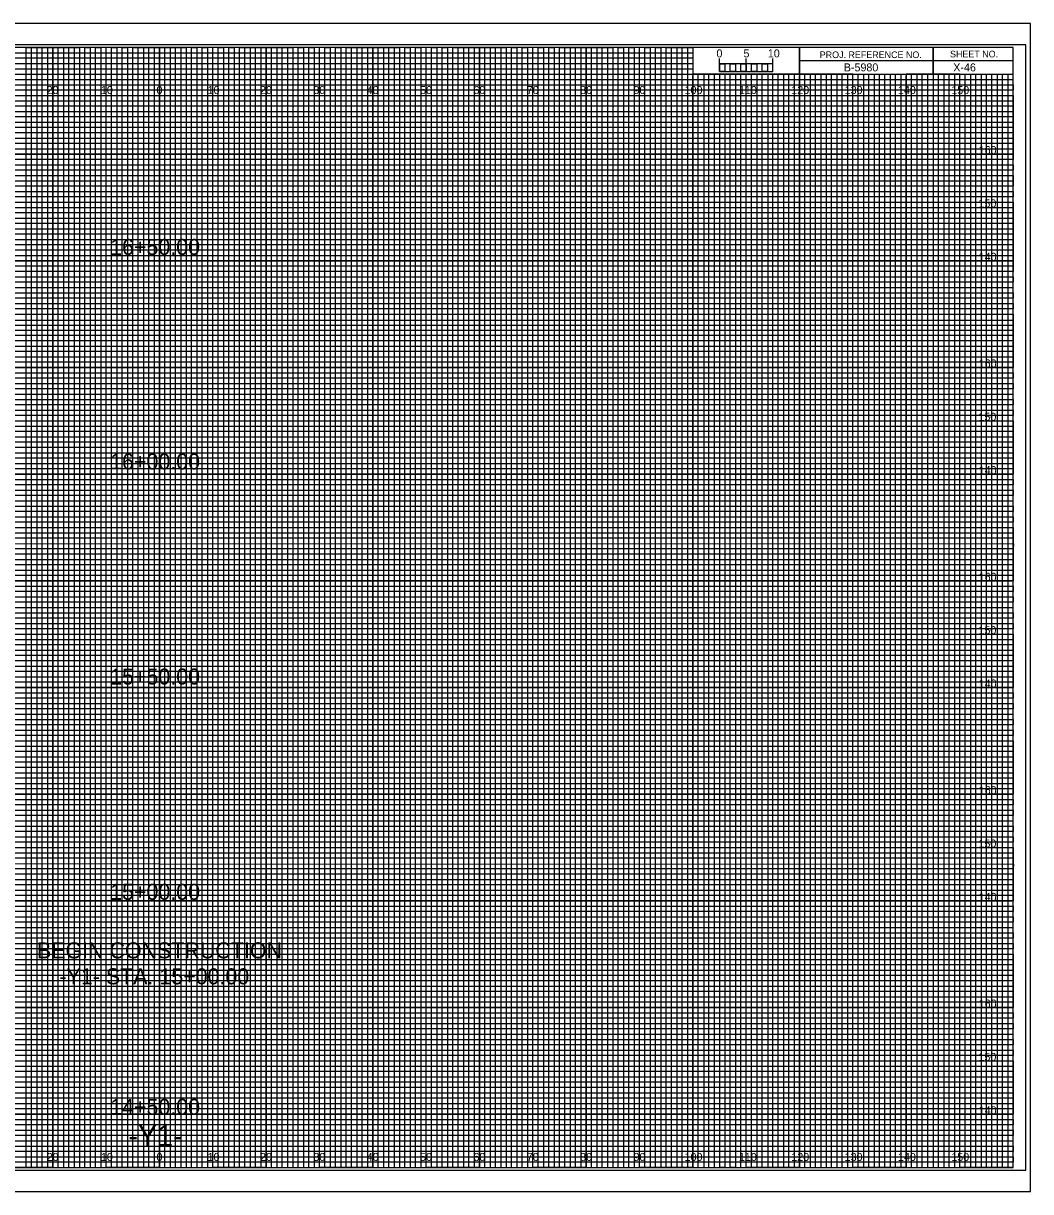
# Model space of a CAD drawing. Extents: x -13 to 323, y -5 to 4834.
# Drawn here: x 134.5 to 323.3, y -4.5 to 214.5 of the extents above; entities that cross this region are included whole.
import ezdxf

# ---------------------------------------------------------------- set-up
doc = ezdxf.new("R2010")
doc.units = 0
for name, color, linetype in [('Exist CMT Pavement', 7, 'Continuous'), ('Exist Cross Section Cell', 7, 'Continuous'), ('Exist XS Center Line Elevation Label', 7, 'Continuous'), ('Exist XS Ground Line', 7, 'Continuous'), ('Prop CMT Pvmt Course 1', 7, 'Continuous'), ('Prop CMT Pvmt Course 1 Wedge', 7, 'Continuous'), ('Prop CMT Pvmt Course 2', 7, 'Continuous'), ('Prop CMT Pvmt Course 2 Wedge', 7, 'Continuous'), ('Prop CMT Pvmt Course 3', 7, 'Continuous'), ('Prop CMT Pvmt Course 3 Wedge', 7, 'Continuous'), ('Prop CMT Pvmt Surface', 7, 'Continuous'), ('Prop CMT Pvmt Surface Shoulder', 7, 'Continuous'), ('Prop CMT Shld Paved Course 1', 7, 'Continuous'), ('Prop CMT Shld Paved Course 2', 7, 'Continuous'), ('Prop CMT Shld Paved Course 3', 7, 'Continuous'), ('Prop CMT Slope Grass', 7, 'Continuous'), ('Prop CMT Subgrade Earthwork', 7, 'Continuous')]:
    doc.layers.add(name, color=color, linetype=linetype)

msp = doc.modelspace()

# ---------------------------------------------------------------- linework, layer by layer
at = {"layer": 'Exist XS Center Line Elevation Label'}
for points in [[(125, 0), (135, 0), (135, 210), (145, 210), (145, 0), (155, 0), (155, 210), (165, 210), (165, 0), (175, 0), (175, 210), (185, 210), (185, 0), (195, 0), (195, 210), (205, 210), (205, 0), (215, 0), (215, 210), (225, 210), (225, 0), (235, 0), (235, 210), (245, 210), (245, 0), (255, 0), (255, 210), (259.93, 210), (260, 210), (260, 205), (264.99, 205), (264.99, 0), (275, 0), (275, 205), (285, 205), (285, 0), (295, 0), (295, 205), (305, 205), (305, 0), (315, 0), (315, 205)], [(0, 205), (275, 205)], [(0, 185), (320, 185), (320, 195), (0, 195)], [(0, 165), (320, 165), (320, 175), (0, 175)], [(0, 145), (320, 145), (320, 155), (0, 155)], [(0, 125), (320, 125), (320, 135), (0, 135)], [(0, 105), (320, 105), (320, 115), (0, 115)], [(0, 85), (320, 85), (320, 95), (0, 95)], [(0, 65), (320, 65), (320, 75), (0, 75)], [(0, 45), (320, 45), (320, 55), (0, 55)], [(0, 25), (320, 25), (320, 35), (0, 35)], [(0, 5), (320, 5), (320, 15), (0, 15)]]:
    msp.add_lwpolyline(points, dxfattribs=at)
at = {"layer": 'Exist XS Ground Line'}
for p, q in [((150, 210), (140, 210)), ((140, 210), (140, 0)), ((150, 0), (150, 210)), ((170, 210), (160, 210)), ((160, 210), (160, 0)), ((170, 0), (170, 210)), ((190, 210), (180, 210)), ((180, 210), (180, 0)), ((190, 0), (190, 210)), ((210, 210), (200, 210)), ((200, 210), (200, 0)), ((210, 0), (210, 210)), ((230, 210), (220, 210)), ((220, 210), (220, 0)), ((230, 0), (230, 210)), ((250, 210), (240, 210)), ((240, 210), (240, 0)), ((250, 0), (250, 210)), ((260, 210), (260, 0)), ((270, 0), (270, 205)), ((290, 205), (280, 205)), ((280, 205), (280, 0)), ((290, 0), (290, 205)), ((310, 205), (300, 205)), ((300, 205), (300, 0)), ((310, 0), (310, 205)), ((140, 0), (130, 0)), ((160, 0), (150, 0)), ((180, 0), (170, 0)), ((200, 0), (190, 0)), ((220, 0), (210, 0)), ((240, 0), (230, 0)), ((260, 0), (250, 0)), ((280, 0), (270, 0)), ((300, 0), (290, 0)), ((320, 0), (310, 0)), ((320, 0), (320, 0))]:
    msp.add_line(p, q, dxfattribs=at)
for points in [[(0, 200), (320, 200), (320, 190), (0, 190)], [(0, 180), (320, 180), (320, 170), (0, 170)], [(0, 160), (320, 160), (320, 150), (0, 150)], [(0, 140), (320, 140), (320, 130), (0, 130)], [(0, 120), (320, 120), (320, 110), (0, 110)], [(0, 100), (320, 100), (320, 90), (0, 90)], [(0, 80), (320, 80), (320, 70), (0, 70)], [(0, 60), (320, 60), (320, 50), (0, 50)], [(0, 40), (320, 40), (320, 30), (0, 30)], [(0, 20), (320, 20), (320, 10), (0, 10)]]:
    msp.add_lwpolyline(points, dxfattribs=at)
at = {"layer": 'Prop CMT Pvmt Course 1'}
for p, q in [((267, 205), (266.01, 205)), ((266.01, 205), (266.01, 0)), ((267, 0), (267, 205)), ((269, 205), (268, 205)), ((268, 205), (268, 0)), ((269, 0), (269, 205)), ((266.01, 0), (265, 0)), ((268, 0), (267, 0))]:
    msp.add_line(p, q, dxfattribs=at)
for points in [[(135, 0), (136, 0), (136, 210), (137, 210), (137, 0)], [(137, 0), (138, 0), (138, 210), (139, 210), (139, 0)], [(140, 0), (141, 0), (141, 210), (142, 210), (142, 0)], [(142, 0), (143, 0), (143, 210), (144, 210), (144, 0)], [(145, 0), (146, 0), (146, 210), (147, 210), (147, 0)], [(147, 0), (148, 0), (148, 210), (149, 210), (149, 0)], [(150, 0), (151, 0), (151, 210), (152, 210), (152, 0)], [(152, 0), (153, 0), (153, 210), (154, 210), (154, 0)], [(155, 0), (156, 0), (156, 210), (157, 210), (157, 0)], [(157, 0), (158, 0), (158, 210), (159, 210), (159, 0)], [(160, 0), (161, 0), (161, 210), (162, 210), (162, 0)], [(162, 0), (163, 0), (163, 210), (164, 210), (164, 0)], [(165, 0), (166, 0), (166, 210), (167, 210), (167, 0)], [(167, 0), (168, 0), (168, 210), (169, 210), (169, 0)], [(170, 0), (171, 0), (171, 210), (172, 210), (172, 0)], [(172, 0), (173, 0), (173, 210), (174, 210), (174, 0)], [(175, 0), (176, 0), (176, 210), (177, 210), (177, 0)], [(177, 0), (178, 0), (178, 210), (179, 210), (179, 0)], [(180, 0), (181, 0), (181, 210), (182, 210), (182, 0)], [(182, 0), (183, 0), (183, 210), (184, 210), (184, 0)], [(185, 0), (186, 0), (186, 210), (187, 210), (187, 0)], [(187, 0), (188, 0), (188, 210), (189, 210), (189, 0)], [(190, 0), (191, 0), (191, 210), (192, 210), (192, 0)], [(192, 0), (193, 0), (193, 210), (194, 210), (194, 0)], [(195, 0), (196, 0), (196, 210), (197, 210), (197, 0)], [(197, 0), (198, 0), (198, 210), (199, 210), (199, 0)], [(200, 0), (201, 0), (201, 210), (202, 210), (202, 0)], [(202, 0), (203, 0), (203, 210), (204, 210), (204, 0)], [(205, 0), (206, 0), (206, 210), (207, 210), (207, 0)], [(207, 0), (208, 0), (208, 210), (209, 210), (209, 0)], [(210, 0), (211, 0), (211, 210), (212, 210), (212, 0)], [(212, 0), (213, 0), (213, 210), (214, 210), (214, 0)], [(215, 0), (216, 0), (216, 210), (217, 210), (217, 0)], [(217, 0), (218, 0), (218, 210), (219, 210), (219, 0)], [(220, 0), (221, 0), (221, 210), (222, 210), (222, 0)], [(222, 0), (223, 0), (223, 210), (224, 210), (224, 0)], [(225, 0), (226, 0), (226, 210), (227, 210), (227, 0)], [(227, 0), (228, 0), (228, 210), (229, 210), (229, 0)], [(230, 0), (231, 0), (231, 210), (232, 210), (232, 0)], [(232, 0), (233, 0), (233, 210), (234, 210), (234, 0)], [(235, 0), (236, 0), (236, 210), (237, 210), (237, 0)], [(237, 0), (238, 0), (238, 210), (239, 210), (239, 0)], [(240, 0), (241, 0), (241, 210), (242, 210), (242, 0)], [(242, 0), (243, 0), (243, 210), (244, 210), (244, 0)], [(245, 0), (246, 0), (246, 210), (247, 210), (247, 0)], [(247, 0), (248, 0), (248, 210), (249, 210), (249, 0)], [(250, 0), (251, 0), (251, 210), (252, 210), (252, 0)], [(252, 0), (253, 0), (253, 210), (254, 210), (254, 0)], [(255, 0), (256, 0), (256, 210), (257, 210), (257, 0)], [(257, 0), (258, 0), (258, 210), (259, 210), (259, 0)], [(260, 0), (261, 0), (261, 205), (262.02, 205), (262.02, 0)], [(262, 0), (263, 0), (263, 205), (263.99, 205), (263.99, 0)], [(270, 0), (270.98, 0), (270.98, 205), (272, 205), (272, 0)], [(272, 0), (273, 0), (273, 205), (274.05, 205), (274.05, 0)], [(275, 0), (276, 0), (276, 205), (277, 205), (277, 0)], [(277, 0), (278, 0), (278, 205), (279, 205), (279, 0)], [(280, 0), (281, 0), (281, 205), (282, 205), (282, 0)], [(282, 0), (283, 0), (283, 205), (284, 205), (284, 0)], [(285, 0), (286, 0), (286, 205), (287, 205), (287, 0)], [(287, 0), (288, 0), (288, 205), (289, 205), (289, 0)], [(290, 0), (291, 0), (291, 205), (292, 205), (292, 0)], [(292, 0), (293, 0), (293, 205), (294, 205), (294, 0)], [(295, 0), (296, 0), (296, 205), (297, 205), (297, 0)], [(297, 0), (298, 0), (298, 205), (299, 205), (299, 0)], [(300, 0), (301, 0), (301, 205), (302, 205), (302, 0)], [(302, 0), (303, 0), (303, 205), (304, 205), (304, 0)], [(305, 0), (306, 0), (306, 205), (307, 205), (307, 0)], [(307, 0), (308, 0), (308, 205), (309, 205), (309, 0)], [(310, 0), (311, 0), (311, 205), (312, 205), (312, 0)], [(312, 0), (313, 0), (313, 205), (314, 205), (314, 0)], [(315, 0), (316, 0), (316, 205), (317, 205), (317, 0)], [(317, 0), (318, 0), (318, 205), (319, 205), (319, 0)]]:
    msp.add_lwpolyline(points, dxfattribs=at)
at = {"layer": 'Prop CMT Pvmt Course 2'}
for p, q in [((323.3, 214.5), (-13.4, 214.5)), ((-13.4, -4.5), (323.3, -4.5))]:
    msp.add_line(p, q, dxfattribs=at)
at = {"layer": 'Prop CMT Pvmt Surface Shoulder'}
for p, q in [((305, 210), (305, 205)), ((305, 205), (305, 210)), ((280, 207.5), (280, 205)), ((320, 207.49), (280, 207.49)), ((280, 205), (320, 205))]:
    msp.add_line(p, q, dxfattribs=at)
for points in [[(320, 210), (0, 210), (0, 0), (320, 0)], [(280, 210), (260, 210), (260, 205.03), (280, 205.03)], [(320, 210), (280, 210), (280, 205), (320, 205)]]:
    msp.add_lwpolyline(points, close=True, dxfattribs=at)
at = {"layer": 'Prop CMT Shld Paved Course 1'}
msp.add_lwpolyline([(-13.4, -4.5), (323.3, -4.5), (323.3, 214.5), (-13.4, 214.5)], close=True, dxfattribs=at)
at = {"layer": 'Prop CMT Shld Paved Course 2'}
msp.add_lwpolyline([(-10.8, -0.5), (322.4, -0.5), (322.4, 210.5), (-10.8, 210.5)], close=True, dxfattribs=at)
at = {"layer": 'Prop CMT Shld Paved Course 3'}
for p, q in [((140, 0), (140, 210)), ((150, 0), (150, 210)), ((160, 0), (160, 210)), ((170, 0), (170, 210)), ((180, 0), (180, 210)), ((190, 0), (190, 210)), ((200, 0), (200, 210)), ((210, 0), (210, 210)), ((220, 0), (220, 210)), ((230, 0), (230, 210)), ((240, 0), (240, 210)), ((250, 0), (250, 210)), ((260, 0), (260, 204.69)), ((270, 0), (270, 204.69)), ((280, 0), (280, 204.69)), ((290, 0), (290, 204.69)), ((300, 0), (300, 204.69)), ((310, 0), (310, 204.69)), ((0, 200), (320, 200)), ((0, 190), (320, 190)), ((0, 180), (320, 180)), ((0, 170), (320, 170)), ((0, 160), (320, 160)), ((0, 150), (320, 150)), ((0, 140), (320, 140)), ((0, 130), (320, 130)), ((0, 120), (320, 120)), ((0, 110), (320, 110)), ((0, 100), (320, 100)), ((0, 90), (320, 90)), ((0, 80), (320, 80)), ((0, 70), (320, 70)), ((0, 60), (320, 60)), ((0, 50), (320, 50)), ((0, 40), (320, 40)), ((0, 30), (320, 30)), ((0, 20), (320, 20)), ((0, 10), (320, 10))]:
    msp.add_line(p, q, dxfattribs=at)
at = {"layer": 'Prop CMT Slope Grass'}
for p, q in [((0, 209), (260, 209)), ((260, 209), (260, 207.98)), ((260, 207.98), (0, 207.98)), ((0, 207), (260, 207)), ((260, 205.89), (0, 205.89)), ((260, 207), (260, 205.89)), ((0, 204), (320, 204))]:
    msp.add_line(p, q, dxfattribs=at)
for points in [[(0, 203), (270, 203), (320, 203), (320, 202), (0, 202)], [(0, 201), (320, 201), (320, 199), (0, 199)], [(0, 198), (320, 198), (320, 197), (0, 196.98)], [(0, 196), (320, 196), (320, 194), (0, 194)], [(0, 193), (320, 193), (320, 192), (0, 192)], [(0, 191), (320, 191), (320, 189), (0, 189)], [(0, 188), (320, 188), (320, 187), (0, 187)], [(0, 186), (320, 186), (320, 184), (0, 184)], [(0, 183), (320, 183), (320, 182), (0, 182)], [(0, 181), (320, 181), (320, 179), (0, 179)], [(0, 178), (320, 178), (320, 177), (0, 177)], [(0, 176), (320, 176), (320, 173.95), (320, 173), (320, 172), (0, 172)], [(0, 174), (320, 174), (320, 173), (0, 173)], [(0, 171), (320, 171), (320, 169), (0, 169.03)], [(0, 169.03), (320, 169), (320, 168), (0, 168)], [(0, 167), (320, 167), (320, 166), (0, 166)], [(0, 164), (320, 164), (320, 163), (0, 163)], [(0, 162), (320, 162), (320, 161), (0, 161)], [(-0.07, 158.89), (320, 158.89), (320, 157.88), (-0.07, 157.88)], [(0, 157), (320, 157), (320, 156), (0, 156)], [(0, 154), (320, 154), (320, 153), (0, 153)], [(0, 152), (320, 152), (320, 151), (0, 151)], [(0, 149), (320, 149), (320, 148), (0, 148)], [(0, 147), (320, 147), (320, 146), (0, 146)], [(0, 144), (320, 144), (320, 143), (0, 143)], [(0, 142), (320, 142), (320, 141), (0, 141)], [(0, 139), (320, 139), (319.99, 137.98), (0, 138)], [(0, 137), (320, 137), (320, 136), (0, 136)], [(0, 134), (320, 134), (320, 133), (0, 133)], [(0, 132), (320, 132), (320, 131), (0, 131)], [(0, 129), (320, 129), (320, 128), (0, 128)], [(0, 127), (320, 127), (320, 126), (0, 126)], [(0, 124), (320, 124), (320, 123), (0, 123)], [(0, 122), (320, 122), (320, 121), (0, 121)], [(0, 119), (320, 119), (320, 118), (0, 118)], [(0, 116.99), (320.07, 116.91), (320, 116), (0, 116)], [(0, 114), (320, 114), (320, 113), (0, 113)], [(0, 112), (320, 112), (320, 111), (0, 111)], [(0, 109), (320, 109), (320, 108), (0, 108)], [(0, 107), (320, 107), (320, 106), (0, 106)], [(0, 104), (320, 104), (320, 103), (0, 103)], [(0, 102), (320, 102), (320, 101), (0, 101)], [(0, 99), (320, 99), (320, 98), (0, 98)], [(0, 97), (320, 97), (320, 96), (0, 96)], [(0, 94), (320, 94), (320, 93), (0, 93)], [(0, 92), (320, 92), (320, 91), (0, 91)], [(0, 89), (320, 89), (320, 88), (0, 88)], [(0, 87), (320, 87), (320, 86), (0, 86)], [(0, 84), (320, 84), (320, 83), (0, 83)], [(0, 82), (320, 82), (320, 81), (0, 81)], [(0, 79), (320, 79), (319.99, 77.98), (0, 78)], [(0, 77), (320, 77), (320, 76), (0, 76)], [(0, 74), (320, 74), (320, 73), (0, 73)], [(0, 72), (320, 72), (320, 71), (0, 71)], [(0, 69), (320, 69), (320, 68), (0, 68)], [(0, 67), (320, 67), (320, 66), (0, 66)], [(0, 64), (320, 64), (320, 63), (0, 63)], [(0, 62), (320, 62), (320, 61), (0, 61)], [(0, 59), (320, 59), (320, 58), (0, 58)], [(0, 56.99), (320.07, 56.91), (320, 56), (0, 56)], [(0, 54), (320, 54), (320, 53), (0, 53)], [(0, 52), (320, 52), (320, 51), (0, 51)], [(0, 49), (320, 49), (320, 48), (0, 48)], [(0, 47), (320, 47), (320, 46), (0, 46)], [(0, 44), (320, 44), (320, 43), (0, 43)], [(0, 42), (320, 42), (320, 41), (0, 41)], [(0, 39), (320, 39), (320, 38), (0, 38)], [(0, 37), (320, 37), (320, 36), (0, 36)], [(0, 34), (320, 34), (320, 33), (0, 33)], [(0, 32), (320, 32), (320, 31), (0, 31)], [(0, 29), (320, 29), (320, 28), (0, 28)], [(0, 27), (320, 27), (320, 26), (0, 26)], [(0, 24), (320, 24), (320, 23), (0, 23)], [(0, 22), (320, 22), (320, 21), (0, 21)], [(0, 19), (320, 19), (320, 18), (0, 18)], [(0, 17), (320, 17), (320, 16), (0, 16)], [(0, 14), (320, 14), (320, 13), (0, 13)], [(0, 12), (320, 12), (320, 11), (0, 11)], [(0, 9), (320, 9), (320, 8), (0, 8)], [(0, 7), (320, 7), (320, 6), (0, 6)], [(0, 4), (320, 4), (320, 3), (0, 3)], [(0, 2), (320, 2), (320, 1), (0, 1)]]:
    msp.add_lwpolyline(points, dxfattribs=at)
at = {"layer": 'Prop CMT Subgrade Earthwork'}
for p, q in [((265, 205.49), (265, 207.9)), ((265, 206.9), (265, 207.9)), ((270, 205.49), (270, 207.9)), ((275, 205.49), (275, 207.9)), ((275, 206.9), (275, 207.9))]:
    msp.add_line(p, q, dxfattribs=at)
for points in [[(275, 206.9), (265, 206.9), (265, 205.49), (275, 205.49)], [(265, 206.9), (266, 206.9), (266, 205.49), (265, 205.49)], [(267, 206.9), (268, 206.9), (268, 205.49), (267, 205.49)], [(269, 206.9), (270, 206.9), (270, 205.49), (269, 205.49)], [(271, 206.9), (272, 206.9), (272, 205.49), (271, 205.49)], [(273, 206.9), (274, 206.9), (274, 205.49), (273, 205.49)]]:
    msp.add_lwpolyline(points, close=True, dxfattribs=at)

# ---------------------------------------------------------------- texts
at = {"layer": 'Exist CMT Pavement'}
msp.add_text('-Y1-', height=4, dxfattribs=at).set_placement((154.21, 4))
at = {"layer": 'Exist Cross Section Cell'}
for s, p in [('20', (138.86, 201.25)), ('10', (149.04, 201.25)), ('0', (159.45, 201.25)), ('0', (159.45, 201.25)), ('10', (169.04, 201.25)), ('20', (178.86, 201.25)), ('30', (188.86, 201.25)), ('40', (198.86, 201.25)), ('50', (208.86, 201.25)), ('60', (218.86, 201.25)), ('70', (228.86, 201.25)), ('80', (238.86, 201.25)), ('90', (248.86, 201.25)), ('100', (258.44, 201.25)), ('110', (268.62, 201.25)), ('120', (278.44, 201.25)), ('130', (288.44, 201.25)), ('140', (298.44, 201.25)), ('150', (308.44, 201.25)), ('20', (138.86, 1.25)), ('10', (149.04, 1.25)), ('0', (159.45, 1.25)), ('0', (159.45, 1.25)), ('10', (169.04, 1.25)), ('20', (178.86, 1.25)), ('30', (188.86, 1.25)), ('40', (198.86, 1.25)), ('50', (208.86, 1.25)), ('60', (218.86, 1.25)), ('70', (228.86, 1.25)), ('80', (238.86, 1.25)), ('90', (248.86, 1.25)), ('100', (258.44, 1.25)), ('110', (268.62, 1.25)), ('120', (278.44, 1.25)), ('130', (288.44, 1.25)), ('140', (298.44, 1.25)), ('150', (308.44, 1.25))]:
    msp.add_text(s, height=1.5, dxfattribs=at).set_placement(p)
at = {"layer": 'Prop CMT Pvmt Course 1 Wedge'}
for s, p in [('16+50.00', (150.77, 171.09)), ('16+00.00', (150.77, 130.87)), ('15+50.00', (150.77, 90.56)), ('15+00.00', (150.77, 50.2)), ('BEGIN CONSTRUCTION', (137.05, 39.23)), ('-Y1- STA. 15+00.00', (141.27, 34.36)), ('14+50.00', (150.77, 9.89))]:
    msp.add_text(s, height=3, dxfattribs=at).set_placement(p)
at = {"layer": 'Prop CMT Pvmt Course 2 Wedge'}
msp.add_text('X-46', height=1.5, dxfattribs=at).set_placement((308.8, 205.5))
at = {"layer": 'Prop CMT Pvmt Course 3'}
for s, p in [('160', (313.57, 190)), ('150', (313.52, 180)), ('140', (313.57, 170)), ('160', (313.57, 150)), ('150', (313.52, 140)), ('140', (313.57, 130)), ('160', (313.57, 110)), ('150', (313.52, 100)), ('140', (313.57, 90)), ('160', (313.57, 70)), ('150', (313.52, 60)), ('140', (313.57, 50)), ('160', (313.57, 30)), ('150', (313.52, 20)), ('140', (313.57, 10))]:
    msp.add_text(s, height=1.5, dxfattribs=at).set_placement(p)
at = {"layer": 'Prop CMT Pvmt Course 3 Wedge'}
msp.add_text('B-5980', height=1.5, dxfattribs=at).set_placement((288.28, 205.5))
at = {"layer": 'Prop CMT Pvmt Surface'}
for s, p in [('5', (269.47, 208.12)), ('10', (274.04, 208.12))]:
    msp.add_text(s, height=1.5, dxfattribs=at).set_placement(p)
at = {"layer": 'Prop CMT Pvmt Surface Shoulder'}
for s, p in [('PROJ. REFERENCE NO.', (283.77, 207.99)), ('SHEET NO.', (308.19, 208.12))]:
    msp.add_text(s, height=1.25, dxfattribs=at).set_placement(p)
at = {"layer": 'Prop CMT Subgrade Earthwork'}
msp.add_text('0', height=1.5, dxfattribs=at).set_placement((264.41, 208.12))

doc.saveas('drawing.dxf')
